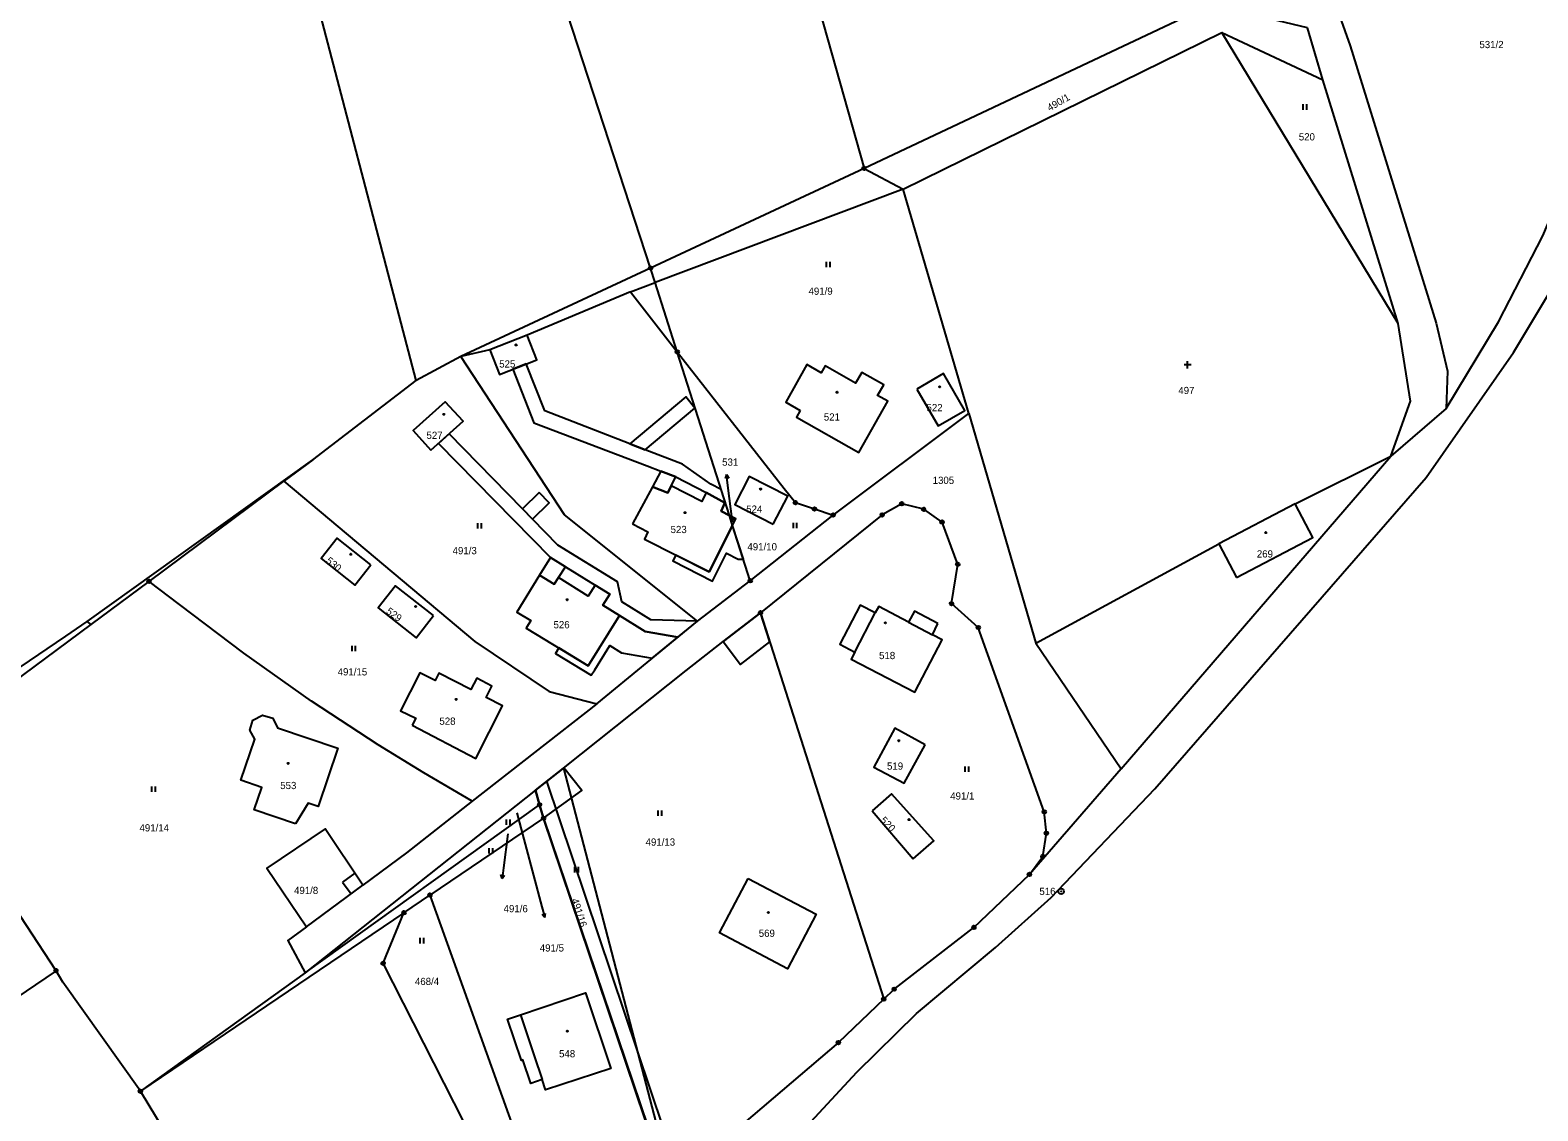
# Model space of a CAD drawing. Extents: x -745926 to -742978, y -968282 to -965689.
# Drawn here: x -744838.5 to -744629.7, y -966471.2 to -966321.6 of the extents above; entities that cross this region are included whole.
import ezdxf

# ---------------------------------------------------------------- set-up
doc = ezdxf.new("R2010")
doc.units = 0
for name, color, linetype in [('Hranice parcel', 7, 'Continuous'), ('Parcelní čísla', 7, 'Continuous'), ('Pop  PČ popisy', 7, 'Continuous'), ('Vnitřní kresba', 7, 'Continuous'), ('Věcná břemena k části', 7, 'Continuous'), ('Značky bodu BP', 7, 'Continuous'), ('Značky budov', 7, 'Continuous'), ('Značky kultur', 7, 'Continuous')]:
    doc.layers.add(name, color=color, linetype=linetype)

msp = doc.modelspace()

# ---------------------------------------------------------------- linework, layer by layer
at = {"layer": 'Hranice parcel'}
for p, q in [((-744745.78, -966259.84), (-744722.98, -966340.71)), ((-744717.55, -966343.61), (-744673.42, -966321.9)), ((-744673.42, -966321.9), (-744659.44, -966328.45)), ((-744649.04, -966362.19), (-744673.42, -966321.9)), ((-744659.44, -966328.45), (-744661.57, -966321.24)), ((-744649.04, -966362.19), (-744659.44, -966328.45)), ((-744722.98, -966340.71), (-744752.55, -966354.51)), ((-744722.98, -966340.71), (-744717.55, -966343.61)), ((-744708.49, -966374.64), (-744717.55, -966343.61)), ((-744741.62, -966388.79), (-744748.85, -966366.12)), ((-744799.31, -966381.07), (-744785, -966370.1)), ((-744727.25, -966388.71), (-744708.49, -966374.64)), ((-744642.37, -966373.98), (-744650.05, -966380.55)), ((-744799.31, -966381.07), (-744803.31, -966384.04)), ((-744687.36, -966423.86), (-744650.05, -966380.55)), ((-744821.99, -966397.9), (-744803.31, -966384.04)), ((-744741.19, -966390.14), (-744741.62, -966388.79)), ((-744738.74, -966397.81), (-744727.25, -966388.71)), ((-744720.47, -966388.69), (-744737.32, -966402.23)), ((-744738.74, -966397.81), (-744741.19, -966390.14)), ((-744737.32, -966402.23), (-744720.25, -966455.74)), ((-744760, -966414.83), (-744777.26, -966428.34)), ((-744768.48, -966426.81), (-744764.61, -966423.74)), ((-744764.61, -966423.74), (-744749.36, -966482.08)), ((-744687.36, -966423.86), (-744700.08, -966438.48)), ((-744768.48, -966426.81), (-744800.37, -966452.12)), ((-744767.9, -966428.82), (-744768.48, -966426.81)), ((-744800.37, -966452.12), (-744767.9, -966428.82)), ((-744767.36, -966430.68), (-744767.9, -966428.82)), ((-744721.87, -966429.69), (-744716.17, -966436.33)), ((-744767.36, -966430.68), (-744783.09, -966441.34)), ((-744749.84, -966482.53), (-744767.36, -966430.68)), ((-744834.87, -966451.8), (-744843.13, -966439.27)), ((-744800.2, -966445.73), (-744792.4, -966439.95)), ((-744786.69, -966443.78), (-744783.09, -966441.34)), ((-744783.09, -966441.34), (-744763.8, -966495.09)), ((-744786.69, -966443.78), (-744823.18, -966468.5)), ((-744800.37, -966452.12), (-744823.18, -966468.5)), ((-744816.75, -966479.01), (-744823.18, -966468.5))]:
    msp.add_line(p, q, dxfattribs=at)
for points in [[(-744752.55, -966354.51), (-744769.07, -966303.83), (-744787.52, -966241.33), (-744803.13, -966183.94), (-744798.68, -966168)], [(-744642.37, -966373.98), (-744635.11, -966361.94), (-744628.97, -966350.04), (-744623.86, -966337.98), (-744619.56, -966326.24), (-744614.79, -966316.26), (-744609.86, -966305.48), (-744598.1, -966290.42), (-744586.67, -966278.15), (-744574.44, -966265.32), (-744561.1, -966253.47), (-744548.95, -966241.36), (-744535.44, -966228.22), (-744521.35, -966211.49), (-744512.98, -966202.49), (-744499.8, -966191.27)], [(-744785, -966370.1), (-744801.12, -966308.48), (-744825.15, -966229.87)], [(-744660.13, -966271.07), (-744662.52, -966286.51), (-744660.55, -966309.96), (-744655.66, -966323.75), (-744643.75, -966362.14), (-744642.18, -966368.78), (-744642.37, -966373.98)], [(-744661.57, -966321.24), (-744674.92, -966318.05), (-744722.98, -966340.71)], [(-744732.11, -966474.62), (-744723.98, -966465.85), (-744715.7, -966457.73), (-744704.77, -966448.58), (-744697.05, -966441.66), (-744682.73, -966426.6), (-744645.14, -966383.49), (-744633.05, -966366.19), (-744624.17, -966351.43)], [(-744752.55, -966354.51), (-744778.82, -966366.77), (-744785, -966370.1)], [(-744748.85, -966366.12), (-744751.91, -966356.53), (-744752.55, -966354.51)], [(-744650.05, -966380.55), (-744647.33, -966372.92), (-744649.04, -966362.19)], [(-744774.82, -966365.82), (-744773.48, -966369.24), (-744768.3, -966367.21), (-744769.65, -966363.79), (-744774.82, -966365.82)], [(-744748.85, -966366.12), (-744734.05, -966385.03), (-744732.49, -966386.99), (-744729.85, -966387.87), (-744727.25, -966388.71)], [(-744731.84, -966374.25), (-744732.35, -966375.17), (-744723.72, -966380.04), (-744719.7, -966372.95), (-744721.1, -966372.17), (-744720.26, -966370.69), (-744723.31, -966368.97), (-744724.15, -966370.45), (-744728.38, -966368.07), (-744728.9, -966369), (-744730.92, -966367.86), (-744733.81, -966373.06), (-744731.84, -966374.25)], [(-744715.69, -966371.26), (-744712.74, -966376.38), (-744709.03, -966374.24), (-744711.98, -966369.12), (-744715.69, -966371.26)], [(-744782.95, -966379.73), (-744778.5, -966375.73), (-744780.99, -966373.03), (-744785.41, -966376.99), (-744782.95, -966379.73)], [(-744708.49, -966374.64), (-744699.2, -966406.44), (-744687.36, -966423.86)], [(-744855.16, -966422.52), (-744856.27, -966420.92), (-744833.52, -966405.47), (-744830.55, -966403.45), (-744799.31, -966381.07)], [(-744735.57, -966389.96), (-744733.54, -966386.11), (-744738.89, -966383.39), (-744740.89, -966387.25), (-744735.57, -966389.96)], [(-744803.31, -966384.04), (-744776.87, -966406.2), (-744766.56, -966413.16), (-744760, -966414.83)], [(-744750.15, -966385.62), (-744752.29, -966384.8), (-744755.04, -966389.95)], [(-744741.62, -966388.79), (-744742.78, -966388.19), (-744742.24, -966387), (-744744.85, -966385.57), (-744745.43, -966386.84), (-744749.67, -966384.68), (-744750.15, -966385.62)], [(-744700.08, -966438.48), (-744698.22, -966435.97), (-744697.73, -966432.77), (-744698.03, -966429.81), (-744707.16, -966404.28), (-744710.86, -966400.98), (-744710, -966395.54), (-744712.17, -966389.69), (-744714.72, -966387.92), (-744717.76, -966387.15), (-744720.47, -966388.69)], [(-744671.4, -966397.34), (-744660.86, -966391.81), (-744663.3, -966387.15), (-744673.85, -966392.68), (-744671.4, -966397.34)], [(-744755.04, -966389.95), (-744752.9, -966391.04), (-744753.4, -966392.03), (-744744.45, -966396.59), (-744741.19, -966390.14)], [(-744741.19, -966390.14), (-744740.73, -966389.24), (-744741.62, -966388.79)], [(-744791.29, -966395.6), (-744795.93, -966391.93), (-744798.15, -966394.74), (-744793.49, -966398.43), (-744791.29, -966395.6)], [(-744855.16, -966422.52), (-744830.02, -966403.86), (-744821.99, -966397.9)], [(-744777.26, -966428.34), (-744783.94, -966424.39), (-744790.26, -966420.53), (-744799.47, -966414.5), (-744808.88, -966407.82), (-744817.75, -966401.12), (-744821.99, -966397.9)], [(-744761.16, -966409.58), (-744756.85, -966402.62), (-744759.14, -966401.2), (-744758.19, -966399.67), (-744760.23, -966398.4), (-744761.18, -966399.93), (-744765.31, -966397.38), (-744765.87, -966398.26), (-744767.94, -966397.02), (-744771.06, -966402.15), (-744769.12, -966403.33), (-744769.79, -966404.38), (-744761.16, -966409.58)], [(-744760, -966414.83), (-744746.06, -966403.41), (-744738.74, -966397.81)], [(-744782.61, -966402.62), (-744787.85, -966398.51), (-744790.26, -966401.58), (-744785.02, -966405.71), (-744782.61, -966402.62)], [(-744764.61, -966423.74), (-744747.61, -966410.25), (-744742.51, -966406.23), (-744737.32, -966402.23)], [(-744712.75, -966403.72), (-744715.99, -966402), (-744716.82, -966403.55), (-744720.95, -966401.37), (-744721.42, -966402.25), (-744723.52, -966401.21), (-744726.34, -966406.57), (-744724.27, -966407.69), (-744724.77, -966408.65), (-744715.96, -966413.23), (-744712.17, -966406), (-744713.5, -966405.3), (-744712.75, -966403.72)], [(-744785.56, -966417.82), (-744776.75, -966422.43), (-744773.04, -966415.15), (-744775.29, -966413.99), (-744774.5, -966412.39), (-744776.6, -966411.31), (-744777.45, -966412.88), (-744781.86, -966410.6), (-744782.38, -966411.62), (-744784.48, -966410.56), (-744787.17, -966415.81), (-744785.06, -966416.86), (-744785.56, -966417.82)], [(-744801.72, -966431.45), (-744807.43, -966429.54), (-744806.36, -966426.45), (-744809.29, -966425.42), (-744807.33, -966419.76), (-744808.04, -966418.51), (-744807.61, -966417.1), (-744806.28, -966416.41), (-744804.85, -966416.85), (-744804.19, -966418.18), (-744795.84, -966420.98), (-744798.56, -966429.07), (-744799.97, -966428.6), (-744801.72, -966431.45)], [(-744714.52, -966420.55), (-744718.74, -966418.22), (-744721.62, -966423.62), (-744717.43, -966425.84), (-744714.52, -966420.55)], [(-744716.17, -966436.33), (-744713.34, -966433.82), (-744719.16, -966427.31), (-744721.87, -966429.69)], [(-744777.26, -966428.34), (-744786.36, -966435.47), (-744792.4, -966439.95)], [(-744792.4, -966439.95), (-744797.62, -966432.17), (-744805.66, -966437.59), (-744800.2, -966445.73)], [(-744834.87, -966451.8), (-744848.92, -966461.33), (-744857.59, -966448.73), (-744843.13, -966439.27)], [(-744739.01, -966439.02), (-744729.6, -966443.98), (-744733.58, -966451.54), (-744743, -966446.54), (-744739.01, -966439.02)], [(-744720.25, -966455.74), (-744718.81, -966454.36), (-744707.76, -966445.81), (-744700.08, -966438.48)], [(-744763.8, -966495.09), (-744769.9, -966489.42), (-744789.58, -966450.78), (-744786.69, -966443.78)], [(-744800.2, -966445.73), (-744802.75, -966447.63), (-744800.37, -966452.12)], [(-744823.18, -966468.5), (-744833.91, -966453.4), (-744834.87, -966451.8)], [(-744767.56, -966466.89), (-744769.13, -966467.41), (-744770.21, -966464.16), (-744770.43, -966464.24), (-744772.35, -966458.52), (-744770.55, -966457.91), (-744761.54, -966454.89), (-744758.06, -966465.33), (-744767.08, -966468.32), (-744767.56, -966466.89)], [(-744720.25, -966455.74), (-744726.53, -966461.76), (-744739.63, -966472.9), (-744749.36, -966482.08)]]:
    msp.add_lwpolyline(points, dxfattribs=at)
at = {"layer": 'Pop  PČ popisy'}
for p, q in [((-744742.03, -966383.12), (-744742.22, -966383.65)), ((-744741.85, -966384.61), (-744742.03, -966383.12)), ((-744742.03, -966383.12), (-744741.72, -966383.59)), ((-744741.19, -966389.67), (-744741.85, -966384.61)), ((-744771.05, -966429.93), (-744767.59, -966442.98)), ((-744772.32, -966432.83), (-744772.91, -966437.54)), ((-744772.91, -966437.54), (-744773.09, -966439.03)), ((-744773.09, -966439.03), (-744773.28, -966438.5)), ((-744773.09, -966439.03), (-744772.78, -966438.56)), ((-744767.59, -966442.98), (-744767.2, -966444.43)), ((-744767.2, -966444.43), (-744767.57, -966444.01)), ((-744767.2, -966444.43), (-744767.09, -966443.88))]:
    msp.add_line(p, q, dxfattribs=at)
at = {"layer": 'Vnitřní kresba'}
for p, q in [((-744717.55, -966343.61), (-744751.91, -966356.53)), ((-744755.34, -966357.82), (-744751.91, -966356.53)), ((-744755.34, -966357.82), (-744769.65, -966363.79)), ((-744755.34, -966357.82), (-744748.85, -966366.12)), ((-744774.82, -966365.82), (-744778.82, -966366.77)), ((-744764.44, -966388.68), (-744778.82, -966366.77)), ((-744663.3, -966387.15), (-744650.05, -966380.55)), ((-744746.06, -966403.41), (-744764.44, -966388.68)), ((-744699.2, -966406.44), (-744673.85, -966392.68)), ((-744724.27, -966407.69), (-744721.42, -966402.25)), ((-744830.02, -966403.86), (-744830.55, -966403.45)), ((-744716.82, -966403.55), (-744713.5, -966405.3)), ((-744770.55, -966457.91), (-744768.65, -966463.61)), ((-744768.65, -966463.61), (-744767.56, -966466.89))]:
    msp.add_line(p, q, dxfattribs=at)
at = {"layer": 'Věcná břemena k části'}
for points in [[(-744742.78, -966388.19), (-744741.62, -966388.79), (-744742.78, -966385.17), (-744744.2, -966384.44), (-744748.13, -966381.65), (-744753.27, -966379.67), (-744755.4, -966378.85), (-744767.2, -966374.3), (-744769.76, -966367.78), (-744771.62, -966368.51), (-744768.7, -966375.96), (-744753.01, -966381.92), (-744751.14, -966382.63), (-744749.03, -966383.43), (-744744.85, -966385.57), (-744742.24, -966387)], [(-744753.27, -966379.67), (-744746.39, -966373.89), (-744747.67, -966372.36), (-744755.4, -966378.85)], [(-744748.77, -966405.63), (-744746.06, -966403.41), (-744752.5, -966403.2), (-744756.5, -966400.72), (-744757.14, -966397.97), (-744765.36, -966392.88), (-744768.87, -966389.28), (-744770.27, -966387.85), (-744780.42, -966377.46), (-744781.91, -966378.79), (-744766.41, -966394.58), (-744764.34, -966395.86), (-744760.23, -966398.4), (-744758.19, -966399.67), (-744759.14, -966401.2), (-744756.85, -966402.62), (-744753.28, -966404.83)], [(-744751.14, -966382.63), (-744752.29, -966384.8), (-744750.15, -966385.62), (-744749.67, -966384.68), (-744749.03, -966383.43)], [(-744767.97, -966385.58), (-744770.27, -966387.85), (-744768.87, -966389.28), (-744766.56, -966387)], [(-744741.19, -966390.14), (-744744.45, -966396.59), (-744749.04, -966394.25), (-744749.45, -966395.05), (-744743.97, -966397.85), (-744743.56, -966397.04), (-744742.02, -966394.01), (-744740.43, -966394.81), (-744739.69, -966394.83)], [(-744766.41, -966394.58), (-744767.94, -966397.02), (-744765.87, -966398.26), (-744765.31, -966397.38), (-744764.34, -966395.86)], [(-744737.32, -966402.23), (-744742.51, -966406.23), (-744740.07, -966409.39), (-744736.04, -966406.26)], [(-744756.85, -966402.62), (-744761.16, -966409.58), (-744765.25, -966407.12), (-744765.71, -966407.89), (-744760.75, -966410.89), (-744760.28, -966410.13), (-744758.2, -966406.77), (-744756.56, -966407.78), (-744752.33, -966408.54), (-744748.77, -966405.63), (-744753.28, -966404.83)], [(-744768.48, -966426.81), (-744767.9, -966428.82), (-744767.36, -966430.68), (-744762.07, -966426.83), (-744764.56, -966423.7)], [(-744768.48, -966426.81), (-744767.9, -966428.82), (-744767.36, -966430.68), (-744749.84, -966482.53), (-744742.57, -966475.68), (-744743.94, -966474.22), (-744748.94, -966478.94), (-744766.9, -966425.56)], [(-744795.2, -966439.53), (-744794.01, -966441.14), (-744792.4, -966439.95), (-744793.51, -966438.29)]]:
    msp.add_lwpolyline(points, close=True, dxfattribs=at)
at = {"layer": 'Značky bodu BP'}
for centre, radius in [((-744722.98, -966340.71), 0.25), ((-744722.98, -966340.71), 0.0152), ((-744752.55, -966354.51), 0.25), ((-744752.55, -966354.51), 0.0152), ((-744748.85, -966366.12), 0.25), ((-744748.85, -966366.12), 0.0152), ((-744732.49, -966386.99), 0.25), ((-744732.49, -966386.99), 0.0152), ((-744729.85, -966387.87), 0.25), ((-744729.85, -966387.87), 0.0152), ((-744717.76, -966387.15), 0.25), ((-744717.76, -966387.15), 0.0152), ((-744714.72, -966387.92), 0.25), ((-744714.72, -966387.92), 0.0152), ((-744727.25, -966388.71), 0.25), ((-744727.25, -966388.71), 0.0152), ((-744720.47, -966388.69), 0.25), ((-744720.47, -966388.69), 0.0152), ((-744712.17, -966389.69), 0.25), ((-744712.17, -966389.69), 0.0152), ((-744710, -966395.54), 0.25), ((-744710, -966395.54), 0.0152), ((-744821.99, -966397.9), 0.25), ((-744821.99, -966397.9), 0.0152), ((-744738.74, -966397.81), 0.25), ((-744738.74, -966397.81), 0.0152), ((-744737.32, -966402.23), 0.25), ((-744737.32, -966402.23), 0.0152), ((-744710.86, -966400.98), 0.25), ((-744710.86, -966400.98), 0.0152), ((-744707.16, -966404.28), 0.25), ((-744707.16, -966404.28), 0.0152), ((-744767.9, -966428.82), 0.25), ((-744767.9, -966428.82), 0.0152), ((-744698.03, -966429.81), 0.25), ((-744767.36, -966430.68), 0.25), ((-744767.36, -966430.68), 0.0152), ((-744698.03, -966429.81), 0.0152), ((-744697.73, -966432.77), 0.25), ((-744697.73, -966432.77), 0.0152), ((-744698.22, -966435.97), 0.25), ((-744698.22, -966435.97), 0.0152), ((-744700.08, -966438.48), 0.25), ((-744700.08, -966438.48), 0.0152), ((-744783.09, -966441.34), 0.25), ((-744783.09, -966441.34), 0.0152), ((-744695.69, -966440.82), 0.375), ((-744695.69, -966440.82), 0.015), ((-744786.69, -966443.78), 0.25), ((-744786.69, -966443.78), 0.0152), ((-744707.76, -966445.81), 0.25), ((-744707.76, -966445.81), 0.0152), ((-744789.58, -966450.78), 0.25), ((-744834.87, -966451.8), 0.25), ((-744834.87, -966451.8), 0.0152), ((-744789.58, -966450.78), 0.0152), ((-744718.81, -966454.36), 0.25), ((-744718.81, -966454.36), 0.0152), ((-744720.25, -966455.74), 0.25), ((-744720.25, -966455.74), 0.0152), ((-744726.53, -966461.76), 0.25), ((-744726.53, -966461.76), 0.0152), ((-744823.18, -966468.5), 0.25), ((-744823.18, -966468.5), 0.0152)]:
    msp.add_circle(centre, radius, dxfattribs=at)
at = {"layer": 'Značky budov'}
for centre, radius in [((-744771.16, -966365.15), 0.0875), ((-744712.5, -966370.96), 0.0875), ((-744726.72, -966371.71), 0.0875), ((-744781.17, -966374.77), 0.0875), ((-744737.31, -966385.11), 0.0875), ((-744747.77, -966388.38), 0.0875), ((-744741.02, -966389.33), 0.0586), ((-744667.35, -966391.14), 0.0875), ((-744794.05, -966394.14), 0.0875), ((-744764.09, -966400.44), 0.0875), ((-744785.06, -966401.38), 0.0875), ((-744720.02, -966403.63), 0.0875), ((-744779.46, -966414.24), 0.0875), ((-744718.17, -966419.96), 0.0875), ((-744802.73, -966423.1), 0.0875), ((-744716.75, -966430.88), 0.0875), ((-744736.22, -966443.75), 0.0875), ((-744764.07, -966460.17), 0.0875)]:
    msp.add_circle(centre, radius, dxfattribs=at)
at = {"layer": 'Značky kultur'}
for p, q in [((-744662.19, -966332.58), (-744662.19, -966331.83)), ((-744661.69, -966332.58), (-744661.69, -966331.83)), ((-744728.16, -966354.39), (-744728.16, -966353.64)), ((-744727.66, -966354.39), (-744727.66, -966353.64)), ((-744677.67, -966367.91), (-744678.67, -966367.91)), ((-744678.17, -966368.41), (-744678.17, -966367.41)), ((-744776.46, -966390.58), (-744776.46, -966389.83)), ((-744775.95, -966390.58), (-744775.95, -966389.83)), ((-744732.77, -966390.53), (-744732.77, -966389.78)), ((-744732.27, -966390.53), (-744732.27, -966389.78)), ((-744793.88, -966407.56), (-744793.88, -966406.81)), ((-744793.38, -966407.56), (-744793.38, -966406.81)), ((-744708.98, -966424.27), (-744708.98, -966423.52)), ((-744708.47, -966424.27), (-744708.47, -966423.52)), ((-744821.6, -966427.04), (-744821.6, -966426.29)), ((-744821.09, -966427.04), (-744821.09, -966426.29)), ((-744751.48, -966430.37), (-744751.48, -966429.62)), ((-744750.97, -966430.37), (-744750.97, -966429.62)), ((-744772.47, -966431.62), (-744772.47, -966430.87)), ((-744771.96, -966431.62), (-744771.96, -966430.87)), ((-744774.89, -966435.57), (-744774.89, -966434.82)), ((-744774.39, -966435.57), (-744774.39, -966434.82)), ((-744763.02, -966438.19), (-744763.02, -966437.44)), ((-744762.52, -966438.19), (-744762.52, -966437.44)), ((-744784.46, -966448.02), (-744784.46, -966447.27)), ((-744783.95, -966448.02), (-744783.95, -966447.27))]:
    msp.add_line(p, q, dxfattribs=at)

# ---------------------------------------------------------------- texts
at = {"layer": 'Parcelní čísla'}
for s, p in [('531/2', (-744637.77, -966324.06)), ('520', (-744662.78, -966336.84)), ('491/9', (-744730.67, -966358.21)), ('525', (-744773.5, -966368.29)), ('497', (-744679.46, -966371.96)), ('522', (-744714.33, -966374.33)), ('521', (-744728.55, -966375.63)), ('527', (-744783.57, -966378.17)), ('531', (-744742.63, -966381.88)), ('1305', (-744713.48, -966384.4)), ('524', (-744739.3, -966388.39)), ('523', (-744749.77, -966391.21)), ('491/3', (-744779.95, -966394.14)), ('491/10', (-744739.13, -966393.6)), ('269', (-744668.59, -966394.59)), ('526', (-744765.98, -966404.39)), ('518', (-744720.9, -966408.66)), ('491/15', (-744795.87, -966410.92)), ('528', (-744781.78, -966417.75)), ('519', (-744719.8, -966423.97)), ('553', (-744803.82, -966426.66)), ('491/1', (-744711.05, -966428.11)), ('491/14', (-744823.31, -966432.52)), ('491/13', (-744753.23, -966434.49)), ('491/8', (-744801.91, -966441.19)), ('491/6', (-744772.89, -966443.71)), ('569', (-744737.56, -966447.12)), ('491/5', (-744767.88, -966449.15)), ('468/4', (-744785.17, -966453.79)), ('548', (-744765.21, -966463.8))]:
    msp.add_text(s, height=1, dxfattribs=at).set_placement(p)
for s, rotation, p in [('490/1', 30, (-744697.27, -966332.83)), ('530', 320, (-744797.58, -966395.19)), ('529', 324, (-744789.25, -966402.24)), ('520', 314, (-744720.81, -966431.06)), ('491/16', 288, (-744763.52, -966441.98))]:
    msp.add_text(s, height=1, rotation=rotation, dxfattribs=at).set_placement(p)
at = {"layer": 'Značky bodu BP'}
msp.add_text('516', height=1, dxfattribs=at).set_placement((-744698.7, -966441.32))

doc.saveas('drawing.dxf')
